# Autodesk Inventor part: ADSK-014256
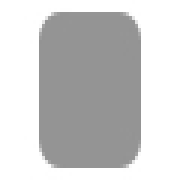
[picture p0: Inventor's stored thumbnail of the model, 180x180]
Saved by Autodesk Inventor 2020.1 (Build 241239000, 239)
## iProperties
Created: 2019-01
Part Number: ADSK-014256
Material: Stahl, weich
Document SubType Name: Modeling
Designer: lutzd
Language: de-DE
Size Designation: 5 x 39,384472 x 39,384472
Categories: <MemberInstance><Categories><Category DisplayName="Sonstige Bauteile" InternalName="5aa15e00-363f-49f2-933f-16f664388e3f" Mnemonic="OTHER"><Category DisplayName
Mass: 60.0398 g
Surface Area: 38.0412 cm^2
Volume: 7.64838 cm^3
Density: 7.85 g/cm^3
Appearance: Semi-Polished(8)
IsCustomPart: 1
Title: end cap
Author: lutzd
Revision Number: -
Dimensions: 39,4x39,4x5 mm
Mass: 0,06 kg
DocNumber: ADSK-014256
Folder: 01 - Themengebiete\Simplification\01 - Packaging machine\ADSK-014200\Frame\
VDS_Category: 3D Komponenten
VDS_NumSchm: Autodesk
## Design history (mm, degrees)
sketch "Sketch1"
  geometry: L1 (0, 20.175)-(0, -21.446); L2 (-20.203, 0)-(20.169, 0); L3 (-19.692, 19.692)-(19.692, 19.692); L4 (19.692, 19.692)-(19.692, -19.692); L5 (19.692, -19.692)-(-19.692, -19.692); L6 (-19.692, -19.692)-(-19.692, 19.692); 1 further point
  constraints: 12 end point, 2 horizontal, 2 parallel, 2 point on line, 1 perpendicular, 1 vertical
  dimensions: "d0" = 39.38447 distance between parallel lines of L5 L3 (= height); "d1" = 19.69224 distance between parallel lines of L2 L3 (= 0.5 x height); "d2" = 39.38447 distance between parallel lines of L6 L4 (= width); "d3" = 19.69224 distance between parallel lines of L6 L1 (= 0.5 x width)
extrude "Extrusion1" new body sketch "Sketch1" distance "d4" = 5 (= thickness); taper "d5" = 0 deg
fillet "Fillet1" dims "d6" = 5 (= fillet), "d7" = 0, "fillet" = 5 [user parameter; used in 1 equation term]
chamfer "Chamfer1" distance "d8" = 0 (computed from chamfer); stored, may be unused: second distance "d9" = 2, angle "d10" = 45 deg; dims "d11" = 0, "chamfer" = 0 [user parameter; used in 1 equation term]
body "Solid1"
other parameters: "thickness" = 5 [user parameter; used in 1 equation term], "width" = 39.38447 [user parameter; used in 2 equation terms], "height" = 39.38447 [user parameter; used in 2 equation terms]
